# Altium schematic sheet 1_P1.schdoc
size 307 x 218 mm; Symbol: Drawing-Symbol_A4; Device: Drawing-Symbol_A4; @Project Name: grandPA2; @Page Count: 1; @Update Date: 2026-07-20; @Create Date: 2026-07-15; @Schematic Name: Key; @Page No: 1; @Page Name: P1; Company: EasyEDA.com; Version: V1.0; Page Size: A4; @Create Time: 08:29:43; @Update Time: 10:12:09; Width: 1170; Height: 825; Region Start: 1; X Region Count: 6; Y Region Count: 4; Blade Width: 10; Title Block Position: 3; @Board Name: Key
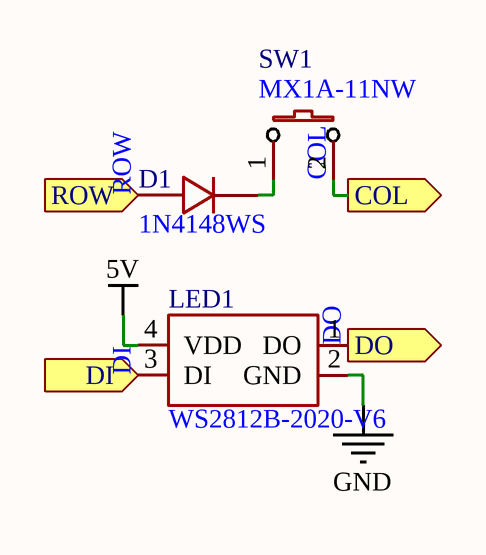
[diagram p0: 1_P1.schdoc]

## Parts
D1  1N4148WS  [SOD-323_L1.8-W1.3-LS2.5-RD]
LED1  WS2812B-2020-V6  [LED-SMD_4P-L2.2-W2.0-P1.00_WS2815C-2020-4P]
SW1  MX1A-11NW  [SW-TH_MX1A-11NW]

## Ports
COL (out), DI (in), DO (out), ROW (in)

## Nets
5V: LED1.4(VDD)
GND: LED1.2(GND)
COL: SW1.2 ; port COL
DI: LED1.3(DI) ; port DI
DO: LED1.1(DO) ; port DO
ROW: D1.2(A) ; port ROW
NetD1_1: D1.1(K) SW1.1

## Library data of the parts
D1 = 1N4148WS_C2128: Manufacturer: CJ(江苏长电/长晶); Symbol: 1N4148WS T4; Add into BOM: yes; Diode Configuration: Standalone; Pd - Power Dissipation: 200mW; Current - Rectified: 150mA; Voltage - DC Reverse(Vr): 100V; Voltage - Forward(Vf@If): 1.25V@150mA; Non-Repetitive Peak Forward Surge Current: 2A; Reverse Leakage Current (Ir): 1uA@75V; Reverse Recovery Time (trr): 4ns
LED1 = WS2812B-2020-V6: Manufacturer: worldsemi; Add into BOM: yes
SW1 = MX1A-11NW: Manufacturer: CHERRY; Add into BOM: yes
